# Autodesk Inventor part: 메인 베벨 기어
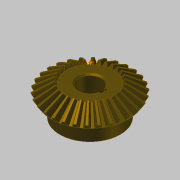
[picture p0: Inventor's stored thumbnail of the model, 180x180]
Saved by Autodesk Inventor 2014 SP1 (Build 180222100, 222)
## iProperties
Created: 2016-04
Part Number: 메인 베벨 기어
Material: 강철, 탄소
Document SubType Name: Modeling
Designer: mdu
Categories: <?xml version="1.0" encoding="UTF-16"?> <MemberInstance><Categories><FamilyTemplate><FamilyTemplateParameter ValueType="xs:double" Id="1" ObjectReferenceKey="da
Mass: 269.926 g
Surface Area: 108.837 cm^2
Volume: 34.2981 cm^3
Density: 7.87 g/cm^3
Appearance: 얼룩무늬
Author: mdu
Revision Number: 1
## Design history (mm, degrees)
node "맨 위 점"
node "메쉬 평면2"
sketch "톱니 본체 스케치"
  geometry: L1 (0, 0)-(28.669, -21.997); L2 (28.669, -21.997)-(31.109, -18.336); L3 (31.109, -18.336)-(0, 0); L4 (30, -20)-(0, 0); L5 (17.219, -13.212)-(18.685, -11.013); L6 (28.669, -21.997)-(17.219, -13.212); L7 (31.109, -18.336)-(18.685, -11.013); L8 (0, -39.387)-(0, 6.564) reference; L9 (0, -20)-(31.109, -20)
  constraints: 16 end point, 4 point on line, 3 perpendicular, 2 collinear, 1 horizontal alignment, 1 vertical alignment
  dimensions: "d0" = 60 diameter of L4.start L8 (= da_de); "d1" = 57.33744 diameter of L1.end L8 (= da_dfe); "d2" = 62.2188 diameter of L2.end L8 (= da_dae); "d3" = 14.4 distance between parallel lines of L2 L5 (= da_b); "d4" = 18.3359 vertical distance of L2.end L1.start (= da_ve)
revolve "톱니 본체" sketch "톱니 본체 스케치" stored, may be unused: angle "d5" = 90 deg
node "시작점"
node "톱니 평면"
sketch "시작 스케치"
  geometry: L1 (0, -23.505)-(0, 10.645) reference; L2 (-0.709, -2.928)-(0.709, -2.928); A1 r 19.188 centre (-19.457, -7.014) between (-0.709, -2.928) and (-3.232, 3.229); A2 r 19.188 centre (19.457, -7.014) between (3.232, 3.229) and (0.709, -2.928); A3 r 57.403 centre (0, -54.083) between (3.232, 3.229) and (-3.232, 3.229); 1 further point
  constraints: 6 point on circle, 3 centre point, 3 symmetric about line, 2 end point, 1 coincident, 1 perpendicular, 1 other
  dimensions: "d7" = 19.18795 radius of A1 (= fd_rr); "d8" = 19.45712 horizontal distance of point (0, -54.083) A1.centre (= fd_x); "d9" = 47.06905 vertical distance of point (0, -54.083) A1.centre (= fd_y); "d57" = 57.40327 radius of A3 (= 0.5 x fd_dva + 0.3 x da_he); "d58" = 51.15527 distance from line of A3.centre L2 (= 0.5 x fd_dva - 1.12 x da_he)
node "끝점"
  node "끝 평면"
sketch "3D 스케치 오른쪽"
  node "Helical Curve Right" dims "d65" = 229.90621 (computed from da_dm, da_delta, da_beta), "d66" = 31.5, "d67" = 60 (= da_de), "d68" = -9.82794 (= -da_delta), "d69" = 8.10972 (computed from fd_loft, da_delta)
node "끝 평면 오른쪽"
sketch "끝 스케치 오른쪽"
  geometry: L1 (0, -41.54)-(0, 13.178) reference; L2 (-0.422, -1.69)-(0.422, -1.69); A1 r 11.427 centre (-11.587, -4.123) between (-0.422, -1.69) and (-1.925, 1.977); A2 r 11.427 centre (11.587, -4.123) between (1.925, 1.977) and (0.422, -1.69); A3 r 34.184 centre (0, -32.153) between (1.925, 1.977) and (-1.925, 1.977); 1 further point
  constraints: 6 point on circle, 3 centre point, 3 symmetric about line, 2 end point, 1 coincident, 1 perpendicular, 1 other
  dimensions: "d70" = 11.58699 horizontal distance of A3.centre A1.centre (computed from fd_x, fd_ratio); "d71" = 28.03028 vertical distance of point (0, -32.153) A1.centre (computed from fd_y, fd_ratio); "d72" = 11.4267 radius of A1 (computed from fd_rr, fd_ratio); "d73" = 30.46369 distance from line of point (0, -32.153) L2 (computed from d58, fd_ratio); "d74" = 34.18446 radius of A3 (computed from d57, fd_ratio)
feature "로프트 오른쪽" sketch "끝 스케치 오른쪽" dims "d75" = 0, "d77" = 0, "d79" = 0, "d80" = 90 deg, "d85" = 20, "d92" = 90 deg, "d93" = 90 deg, "da_teethtype" = 0 [user parameter]
sketch "3D 스케치 왼쪽"
  node "Helical Curve Left" dims "d26" = 229.90621 (computed from da_dm, da_delta, da_beta), "d27" = 8.10972 (computed from fd_loft, da_delta), "d28" = 60 (= da_de), "d29" = -9.82794 (= -da_delta)
node "끝 평면 왼쪽"
sketch "끝 스케치 왼쪽" dims "d56" = 10.3728 (derived)
  geometry: L1 (0, -43.753)-(0, 15.405) reference; L2 (-0.422, -1.678)-(0.422, -1.678); A1 r 11.427 centre (-11.587, -4.111) between (-0.422, -1.678) and (-1.925, 1.988); A2 r 11.427 centre (11.587, -4.111) between (1.925, 1.988) and (0.422, -1.678); A3 r 34.184 centre (0, -32.142) between (1.925, 1.988) and (-1.925, 1.988); 2 further points; 1 other entity
  constraints: 6 point on circle, 3 centre point, 3 symmetric about line, 2 end point, 1 coincident, 2 other
  dimensions: "d30" = 11.4267 radius of A1 (computed from fd_rr, fd_ratio); "d31" = 11.58699 horizontal distance of point (0, -32.142) A1.centre (computed from fd_x, fd_ratio); "d32" = 28.03028 vertical distance of A1.centre point (0, -32.142) (computed from fd_y, fd_ratio); "d61" = 34.18446 radius of A3 (computed from d57, fd_ratio); "d62" = 30.46369 distance from line of point (0, -32.142) L2 (computed from d58, fd_ratio)
feature "로프트 왼쪽" sketch "끝 스케치 왼쪽" dims "d35" = 0, "d37" = 0, "d39" = 0, "d40" = 90 deg, "d84" = 10, "d90" = 90 deg, "d91" = 90 deg, "da_teethtype" = 0 [user parameter]
sketch "본체 스케치"
  geometry: L1 (0, -35.038)-(0, -19.531) reference; L2 (28.669, -21.997)-(17.219, -13.212) reference; L3 (17.219, -13.212)-(0, -13.212); L4 (28.669, -21.997)-(0, -21.997)
  constraints: 4 end point, 2 perpendicular, 2 point on line
revolve "본체 고정" sketch "본체 스케치" stored, may be unused: angle "d46" = 90 deg
feature "피치 지름" dims angle "d47" = 90 deg
sketch "스케치8"
  geometry: C1 r 22.5 at (0, 0); 1 further point
  constraints: 1 centre point, 1 coincident
  dimensions: "d94" = 45 diameter of C1
extrude "돌출1" join sketch "스케치8" distance "d95" = 13; taper "d96" = 0 deg
sketch "스케치9"
  geometry: 1 further point
hole "구멍1" sketch "스케치9" at (0, 0) diameter "d97" = 17; stored, may be unused: countersink angle "d101" = 90 deg, drill point angle "d103" = 118 deg; dims "d98" = 6, "d99" = 4, "d100" = 2, "d102" = 8
sketch "스케치10"
  geometry: L1 (8.124, 2.5)-(10.8, 2.5); L2 (10.8, 2.5)-(10.8, -2.5); L3 (10.8, -2.5)-(8.124, -2.5); A1 r 8.5 centre (0, 0) between (8.124, 2.5) and (8.124, -2.5) reference; 1 further point
  constraints: 6 end point, 2 parallel, 2 point on circle, 1 horizontal, 1 perpendicular
  dimensions: "d104" = 5 distance of L1.end L2.end; "d112" = 19.3 dimension on A1 L2
extrude "돌출2" cut sketch "스케치10" stored distance "d106" = 10; taper "d107" = 0 deg
chamfer "모따기1" distance "d108" = 1; stored, may be unused: second distance "d109" = 2, angle "d110" = 45 deg
fillet "모깎기1" dims "d111" = 2
body "Solid1"
feature "로프트" dims "d17" = 0, "d18" = 90 deg, "d19" = 0, "d20" = 90 deg, "d89" = 0, "da_teethtype" = 0 [user parameter]
pattern_circular "원형 패턴" dims angle "d22" = 360 deg, "d88" = 0, "da_teethtype" = 0 [user parameter]
pattern_circular "원형 패턴 오른쪽" dims angle "d82" = 360 deg, "da_teethtype" = 0 [user parameter]
pattern_circular "원형 패턴 왼쪽" dims angle "d42" = 360 deg, "da_teethtype" = 0 [user parameter]
sketch "끝 스케치"
  geometry: L1 (0, -15.359)-(0, 6.983) reference; L2 (-0.422, -1.69)-(0.422, -1.69); A1 r 11.427 centre (-11.587, -4.123) between (-0.422, -1.69) and (-1.925, 1.977); A2 r 11.427 centre (11.587, -4.123) between (1.925, 1.977) and (0.422, -1.69); A3 r 34.184 centre (0, -32.153) between (1.925, 1.977) and (-1.925, 1.977); 1 further point
  constraints: 6 point on circle, 3 centre point, 3 symmetric about line, 2 end point, 1 coincident, 1 other
  dimensions: "d12" = 11.4267 radius of A1 (computed from fd_rr, fd_ratio); "d15" = 11.58699 horizontal distance of A1.centre point (0, -32.153) (computed from fd_x, fd_ratio); "d16" = 28.03028 vertical distance of A1.centre point (0, -32.153) (computed from fd_y, fd_ratio); "d59" = 34.18446 radius of A3 (computed from d57, fd_ratio); "d60" = 30.46369 distance from line of A3.centre L2 (computed from d58, fd_ratio)
sketch "Sketch6"
  geometry: L1 (30, -20)-(0, 0) reference; L2 (0, -37.8)-(0, 6.3) reference
body "Srf1"
other parameters: "da_b" = 14.4 [user parameter; used in 2 equation terms], "da_de" = 60 [user parameter; used in 4 equation terms], "da_dae" = 62.2188 [user parameter; used in 2 equation terms], "da_dfe" = 57.33744 [user parameter; used in 1 equation term], "da_le" = 36.05551 [user parameter; used in 1 equation term], "da_omega" = 90 deg [user parameter; used in 1 equation term], "da_beta" = 0 [user parameter; used in 2 equation terms], "da_delta" = 9.82794 [user parameter; used in 8 equation terms], "da_alpha" = 20 deg [user parameter; used in 2 equation terms], "da_he" = 4.4 [user parameter; used in 4 equation terms], "da_ve" = 18.3359 [user parameter; used in 1 equation term], "fd_dv" = 108.16654 (computed from da_de, da_delta) [user parameter; used in 1 equation term], "fd_dva" = 112.16654 (computed from da_dae, da_delta) [user parameter; used in 3 equation terms], "fd_dvb" = 101.6433 (computed from fd_dv, da_alpha) [user parameter; used in 2 equation terms], "da_zv" = 540.83269 [user parameter; used in 1 equation term], "fd_loft" = 14.62 (= da_b + 0.05 x da_he) [user parameter; used in 4 equation terms], "fd_ratio" = 5.95514 (computed from da_le, fd_loft) [user parameter; used in 15 equation terms], "fd_rr" = 19.18795 (computed from fd_dd, fd_dvb) [user parameter; used in 6 equation terms], "fd_angle" = 0.29367 (computed from da_zv) [user parameter; used in 4 equation terms], "fd_x1" = 1.58802 (computed from da_dvw, fd_angle) [user parameter; used in 1 equation term], "fd_y1" = 54.05995 (computed from da_dvw, fd_angle) [user parameter; used in 1 equation term], "fd_x2" = 17.8691 (computed from fd_rr, fd_angle2, fd_angle) [user parameter; used in 1 equation term], "fd_y2" = 6.9909 (computed from fd_rr, fd_angle2, fd_angle) [user parameter; used in 1 equation term], "fd_x" = 19.45712 (= fd_x1 + fd_x2) [user parameter; used in 4 equation terms], "fd_y" = 47.06905 (= fd_y1 - fd_y2) [user parameter; used in 4 equation terms], "fd_angle2" = 3.43555 (computed from fd_dvb, fd_dd, da_alpha) [user parameter; used in 2 equation terms], "fd_dd" = 108.64654 (= fd_dva - 0.8 x da_he) [user parameter; used in 2 equation terms], "da_dvw" = 108.16654 [user parameter; used in 2 equation terms], "d11" = 14.62 (= fd_loft), "da_dm" = 48.01848 [user parameter; used in 2 equation terms], "da_x" = 0 [user parameter], "da_m" = 2 [user parameter], "d48" = 0, "d49" = 0, "d50" = 90 deg (= da_omega), "d51" = 6 deg (computed from da_z), "d52" = 0, "d53" = 0, "d54" = 0
